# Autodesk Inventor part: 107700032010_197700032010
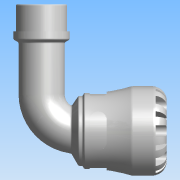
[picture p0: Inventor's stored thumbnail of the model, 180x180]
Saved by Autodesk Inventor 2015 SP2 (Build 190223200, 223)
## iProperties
Created: 2016-12
Part Number: 107700032010_197700032010
Material: PVC-Piping
Description: PLASSON 90° ELBOW WITH MALE INTEGRAL BRASS 32X1" SERIES 1
Document SubType Name: Modeling
Designer: KIM
Mass: 664.223 g
Surface Area: 733.008 cm^2
Volume: 474.445 cm^3
Density: 1.4 g/cm^3
Appearance: Smooth - White
Author: KIM
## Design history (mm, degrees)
derived "1077.ipt"
feature "Solid1::1077.ipt"
tag "TaggingFeature1"
body "Solid1"
other parameters: "d1" = 22.68, "d2" = 32, "d4" = 58, "d8" = 49.3, "d13" = 7.2, "d14" = 7.2, "d15" = 0, "d17" = 360 deg, "d19" = 8 deg, "d20" = 0.64, "d21" = 0.64, "d22" = 8 deg, "d24" = 0, "d26" = 360 deg, "d33" = 5.8, "d43" = 45.24, "d51" = 0.58, "d54" = 11.2, "d55" = 7.04, "d57" = 14.112, "d58" = 0, "d74" = 0, "d78" = 54, "d82" = 0.64, "d115" = 360 deg, "d207" = 90 deg, "d228" = 9.52, "d247" = 1.16, "d248" = 3.24, "d268" = 27.115, "d269" = 3.24, "d270" = 81, "d276" = 33.249, "d277" = 17.5, "d278" = 36.5739, "d279" = 82, "d280" = 22.75, "d281" = 4.98735, "d283" = 29.9241, "d286" = 0, "d287" = 0, "d288" = 23.2743, "d290" = 7.65795, "d292" = 30 deg, "d294" = 3.3249, "d296" = 30 deg, "d_" = 32, "E_" = 58, "l_" = 54, "A_" = 81, "A_1" = 82, "l_2" = 17.5, "R_" = 33.249, "d9" = 9, "d11" = 58, "d289" = 23.2743
